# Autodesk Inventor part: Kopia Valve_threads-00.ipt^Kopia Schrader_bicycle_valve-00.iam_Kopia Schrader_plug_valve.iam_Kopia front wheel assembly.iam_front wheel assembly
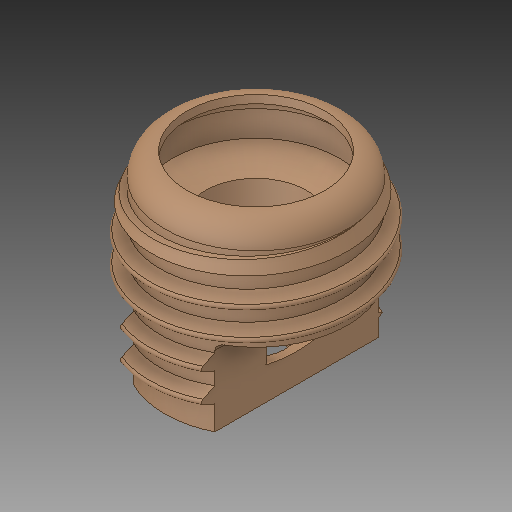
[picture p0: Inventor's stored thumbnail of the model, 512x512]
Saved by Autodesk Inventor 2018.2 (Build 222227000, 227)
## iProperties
Created: 2017-09
Part Number: Kopia Valve_threads-00.ipt^Kopia Schrader_bicycle_valve-00.iam_Kopia Schrader_plug_valve.iam_Kopia front wheel assembly.iam_front wheel assembly
Material: Ogólny
Document SubType Name: Modeling
Designer: Tomasz
Density: 1 g/cm^3
Appearance: Domyślna
Author: Tomasz
Sending System: SolidWorks 2017
Last Author: Tomasz
Last Saved: 2017-09-11
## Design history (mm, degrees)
feature "Valve_threads-00.ipt"
node "Bryła1"
